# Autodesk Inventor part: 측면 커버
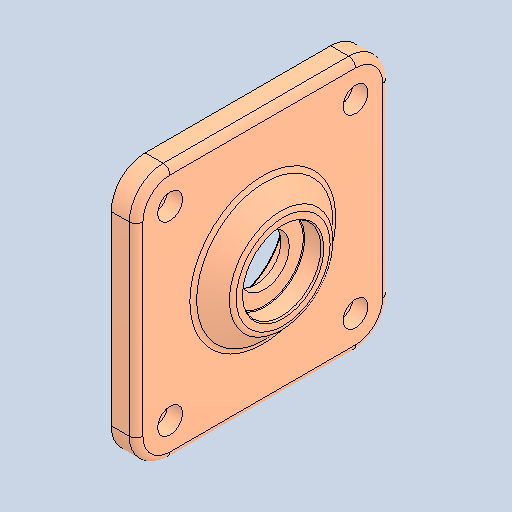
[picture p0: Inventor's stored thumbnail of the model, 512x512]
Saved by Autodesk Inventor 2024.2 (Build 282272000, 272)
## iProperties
Created: 2026-01
Part Number: 측면 커버
Material: 알루미늄 6061
Document SubType Name: Modeling
Designer: home
Density: 2.7 g/cm^3
Appearance: 기본값
Author: jhkim
Sending System: Autodesk Inventor 2026
Preprocessor: ST-DEVELOPER v20.1
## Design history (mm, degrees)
feature "솔리드1"
node "솔리드2"
